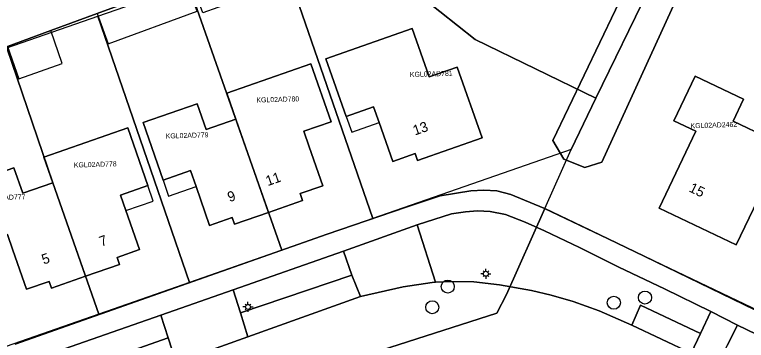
# Model space of a CAD drawing. Extents: x 124901 to 125496, y 515369 to 515789.
# Drawn here: x 125375.1 to 125447.9, y 515610.2 to 515642.6 of the extents above; entities that cross this region are included whole.
import ezdxf

# ---------------------------------------------------------------- set-up
doc = ezdxf.new("R2010")
doc.units = 0
for name, color, linetype in [('Gebouw', 7, 'Continuous'), ('Inrit', 7, 'Continuous'), ('Lichtmast', 7, 'Continuous'), ('Luifel', 7, 'Continuous'), ('Onbegroeid terrein', 7, 'Continuous'), ('Parkeren', 7, 'Continuous'), ('Perceelnummers', 7, 'Continuous'), ('Perceelsgrenzen', 7, 'Continuous'), ('Putten', 7, 'Continuous'), ('Teksten', 7, 'Continuous'), ('Vegetatie', 7, 'Continuous'), ('Voetpad', 7, 'Continuous'), ('Water', 7, 'Continuous'), ('Wegen lokale weg', 7, 'Continuous')]:
    doc.layers.add(name, color=color, linetype=linetype)

msp = doc.modelspace()

# ---------------------------------------------------------------- linework, layer by layer
at = {"layer": 'Gebouw'}
for points in [[(125410.844, 515633.424), (125411.39, 515631.867), (125412.745, 515628.002), (125414.976, 515628.779), (125415.215, 515628.092), (125421.655, 515630.332), (125419.151, 515637.368), (125416.368, 515636.398), (125414.688, 515641.218), (125406.105, 515638.212), (125408.119, 515632.469)], [(125404.595, 515637.692), (125396.253, 515634.781), (125397.145, 515632.216), (125400.378, 515622.922), (125403.778, 515624.105), (125403.539, 515624.794), (125405.794, 515625.578), (125404.439, 515629.441), (125403.893, 515630.998), (125406.608, 515631.951)], [(125442.903, 515630.992), (125439.24, 515623.35), (125446.92, 515619.7), (125450.354, 515626.876), (125453.96, 515625.15), (125456.99, 515631.45), (125451.94, 515633.89), (125450.218, 515630.285), (125446.609, 515632.009), (125447.646, 515634.179), (125442.84, 515636.475), (125440.719, 515632.035)], [(125394.169, 515631.178), (125393.28, 515633.72), (125387.91, 515631.86), (125389.902, 515626.132), (125392.638, 515627.083), (125393.186, 515625.506), (125394.53, 515621.64), (125396.77, 515622.42), (125397.004, 515621.748), (125400.378, 515622.922), (125397.145, 515632.216)], [(125385.565, 515617.762), (125385.325, 515618.452), (125387.565, 515619.232), (125386.202, 515623.109), (125385.661, 515624.647), (125388.392, 515625.607), (125386.375, 515631.342), (125378.036, 515628.433), (125378.931, 515625.866), (125382.17, 515616.578)], [(125375.063, 515627.374), (125369.695, 515625.503), (125371.671, 515619.772), (125374.406, 515620.725), (125374.949, 515619.167), (125376.301, 515615.284), (125378.556, 515616.07), (125378.79, 515615.399), (125382.17, 515616.578), (125378.931, 515625.866), (125375.951, 515624.827)]]:
    msp.add_lwpolyline(points, close=True, dxfattribs=at)
at = {"layer": 'Inrit'}
for points in [[(125409.531, 515614.567), (125413.775, 515615.518), (125416.656, 515615.975), (125416.988, 515615.988), (125415.182, 515621.683), (125407.837, 515619.085), (125408.68, 515616.693)], [(125389.667, 515612.721), (125390.406, 515610.469), (125391.211, 515608.016), (125398.324, 515610.559), (125397.585, 515612.935), (125396.869, 515615.238)], [(125447.051, 515611.707), (125444.402, 515613.086), (125443.375, 515610.9), (125442.448, 515608.927), (125445.037, 515607.711), (125446.027, 515609.707)]]:
    msp.add_lwpolyline(points, close=True, dxfattribs=at)
at = {"layer": 'Lichtmast'}
for p, q in [((125421.803, 515617.037), (125421.733, 515617.108)), ((125422.015, 515617.125), (125422.015, 515617.325)), ((125422.227, 515617.037), (125422.298, 515617.109)), ((125421.715, 515616.826), (125421.515, 515616.825)), ((125421.803, 515616.613), (125421.731, 515616.542)), ((125422.015, 515616.525), (125422.015, 515616.325)), ((125422.227, 515616.613), (125422.297, 515616.542)), ((125422.315, 515616.825), (125422.515, 515616.825)), ((125398.345, 515613.83), (125398.345, 515614.03)), ((125398.045, 515613.531), (125397.845, 515613.53)), ((125398.133, 515613.318), (125398.061, 515613.247)), ((125398.133, 515613.742), (125398.063, 515613.813)), ((125398.345, 515613.23), (125398.345, 515613.03)), ((125398.557, 515613.742), (125398.628, 515613.814)), ((125398.557, 515613.318), (125398.627, 515613.247)), ((125398.645, 515613.53), (125398.845, 515613.53))]:
    msp.add_line(p, q, dxfattribs=at)
for centre in [(125422.015, 515616.825), (125398.345, 515613.53)]:
    msp.add_circle(centre, 0.25, dxfattribs=at)
at = {"layer": 'Luifel'}
for points in [[(125392.17, 515645.96), (125383.332, 515642.723), (125384.436, 515639.707), (125393.275, 515642.944)], [(125374.409, 515639.418), (125375.532, 515636.224), (125379.873, 515637.75), (125378.729, 515641.005)], [(125411.39, 515631.867), (125410.844, 515633.424), (125408.119, 515632.469), (125408.665, 515630.912)], [(125389.902, 515626.132), (125390.45, 515624.555), (125393.186, 515625.506), (125392.638, 515627.083)], [(125388.392, 515625.607), (125385.661, 515624.647), (125386.202, 515623.109), (125388.914, 515624.062)]]:
    msp.add_lwpolyline(points, close=True, dxfattribs=at)
at = {"layer": 'Onbegroeid terrein'}
for points in [[(125429.798, 515702.583), (125421.887, 515685.97), (125412.818, 515667.163), (125406.911, 515654.851), (125405.36, 515651.11), (125405.288, 515650.687), (125401.387, 515649.315), (125397.596, 515647.927), (125395.619, 515647.21), (125396.839, 515643.846), (125393.848, 515642.761), (125392.627, 515646.124), (125392.17, 515645.96), (125383.332, 515642.723), (125378.729, 515641.005), (125374.409, 515639.418)], [(125490.925, 515630.677), (125448.027, 515651.268), (125444.728, 515651.073), (125443.321, 515649.329), (125433.556, 515627.939), (125431.85, 515627.386), (125429.766, 515628.208), (125428.663, 515630.094), (125436.481, 515646.34), (125445.451, 515665.509), (125446.119, 515665.186), (125448.787, 515670.727), (125448.083, 515671.163), (125452.441, 515680.669), (125457.131, 515690.833)], [(125375.169, 515609.812), (125392.301, 515615.845), (125406.232, 515620.771), (125414.095, 515623.452), (125417.469, 515624.564), (125420.516, 515625.062), (125421.795, 515625.138), (125423.115, 515625.058), (125424.478, 515624.722), (125427.773, 515623.362), (125434.165, 515620.296), (125439.534, 515617.72), (125451.494, 515611.999), (125464.767, 515605.477)]]:
    msp.add_lwpolyline(points, dxfattribs=at)
for points in [[(125411.39, 515631.867), (125410.844, 515633.424), (125408.119, 515632.469), (125406.105, 515638.212), (125414.688, 515641.218), (125416.368, 515636.398), (125419.151, 515637.368), (125421.655, 515630.332), (125415.215, 515628.092), (125414.976, 515628.779), (125412.745, 515628.002)], [(125393.28, 515633.72), (125394.169, 515631.178), (125397.145, 515632.216), (125396.253, 515634.781), (125404.595, 515637.692), (125406.608, 515631.951), (125403.893, 515630.998), (125404.439, 515629.441), (125405.794, 515625.578), (125403.539, 515624.794), (125403.778, 515624.105), (125400.378, 515622.922), (125397.004, 515621.748), (125396.77, 515622.42), (125394.53, 515621.64), (125393.186, 515625.506), (125392.638, 515627.083), (125389.902, 515626.132), (125387.91, 515631.86)], [(125439.24, 515623.35), (125442.903, 515630.992), (125440.719, 515632.035), (125442.84, 515636.475), (125447.646, 515634.179), (125446.609, 515632.009), (125450.218, 515630.285), (125451.94, 515633.89), (125456.99, 515631.45), (125453.96, 515625.15), (125450.354, 515626.876), (125446.92, 515619.7)], [(125369.695, 515625.503), (125375.063, 515627.374), (125375.951, 515624.827), (125378.931, 515625.866), (125378.036, 515628.433), (125386.375, 515631.342), (125388.392, 515625.607), (125385.661, 515624.647), (125386.202, 515623.109), (125387.565, 515619.232), (125385.325, 515618.452), (125385.565, 515617.762), (125382.17, 515616.578), (125378.79, 515615.399), (125378.556, 515616.07), (125376.301, 515615.284), (125374.949, 515619.167), (125374.406, 515620.725), (125371.671, 515619.772)]]:
    msp.add_lwpolyline(points, close=True, dxfattribs=at)
at = {"layer": 'Parkeren'}
for points in [[(125397.585, 515612.935), (125398.324, 515610.559), (125409.531, 515614.567), (125408.68, 515616.693)], [(125442.448, 515608.927), (125443.375, 515610.9), (125437.399, 515613.708), (125436.536, 515611.705)], [(125379.481, 515606.624), (125380.382, 515604.143), (125391.211, 515608.016), (125390.406, 515610.469)]]:
    msp.add_lwpolyline(points, close=True, dxfattribs=at)
at = {"layer": 'Perceelsgrenzen'}
for points in [[(125374.35, 515639.28), (125383.42, 515642.43), (125392.439, 515645.595), (125401.6, 515648.81), (125405.36, 515651.11), (125407.38, 515655.81), (125411.516, 515664.357), (125417.983, 515677.745), (125422.606, 515687.317), (125424.5, 515691.221)], [(125352.068, 515590.151), (125423.088, 515612.915), (125424.074, 515614.767), (125427.879, 515623.328), (125430.488, 515629.198), (125410.753, 515622.315), (125401.726, 515619.167), (125392.524, 515615.957), (125389.12, 515614.77), (125383.515, 515612.815), (125374.301, 515609.602)], [(125464.319, 515605.693), (125448.8, 515613.204), (125432.377, 515621.151), (125427.879, 515623.328), (125424.074, 515614.767), (125423.088, 515612.915), (125352.068, 515590.151)]]:
    msp.add_lwpolyline(points, dxfattribs=at)
for points in [[(125405.36, 515651.11), (125407.38, 515655.81), (125411.516, 515664.357), (125440.645, 515650.271), (125438.238, 515645.132), (125432.962, 515634.284), (125420.94, 515640.11), (125410.39, 515648.52)], [(125410.753, 515622.315), (125401.6, 515648.81), (125405.36, 515651.11), (125410.39, 515648.52), (125420.94, 515640.11), (125432.962, 515634.284), (125430.488, 515629.198)], [(125458.523, 515632.331), (125454.483, 515623.931), (125454.428, 515623.816), (125453.982, 515624.032), (125448.8, 515613.204), (125432.377, 515621.151), (125427.879, 515623.328), (125430.488, 515629.198), (125432.962, 515634.284), (125438.238, 515645.132), (125440.645, 515650.271), (125440.672, 515650.329), (125443.053, 515649.181), (125462.19, 515639.955), (125462.144, 515639.859), (125461.924, 515639.69), (125461.215, 515638.361), (125459.902, 515635.812), (125458.642, 515633.35)], [(125401.726, 515619.167), (125392.439, 515645.595), (125401.6, 515648.81), (125410.753, 515622.315)], [(125392.524, 515615.957), (125383.42, 515642.43), (125392.439, 515645.595), (125401.726, 515619.167)], [(125374.35, 515639.28), (125383.42, 515642.43), (125392.524, 515615.957), (125389.12, 515614.77), (125383.515, 515612.815), (125378.923, 515625.863)], [(125374.301, 515609.602), (125365.21, 515636.12), (125368.75, 515637.34), (125374.35, 515639.28), (125378.923, 515625.863), (125383.515, 515612.815)]]:
    msp.add_lwpolyline(points, close=True, dxfattribs=at)
at = {"layer": 'Putten'}
for centre in [(125418.22, 515615.55), (125437.84, 515614.46), (125416.68, 515613.5), (125434.74, 515613.95)]:
    msp.add_circle(centre, 0.65, dxfattribs=at)
at = {"layer": 'Vegetatie'}
msp.add_lwpolyline([(125374.409, 515639.418), (125378.729, 515641.005), (125383.332, 515642.723), (125392.17, 515645.96), (125392.627, 515646.124), (125395.619, 515647.21), (125397.596, 515647.927), (125401.387, 515649.315), (125405.288, 515650.687), (125405.36, 515651.11), (125406.911, 515654.851), (125389.202, 515648.653), (125381.355, 515645.99), (125372.6, 515642.854)], dxfattribs=at)
for points in [[(125443.375, 515610.9), (125444.402, 515613.086), (125439.775, 515615.327), (125435.239, 515617.475), (125431.321, 515619.424), (125427.838, 515621.112), (125425.93, 515621.968), (125423.967, 515622.72), (125422.437, 515623.018), (125421.168, 515623.076), (125419.985, 515622.996), (125418.603, 515622.78), (125415.182, 515621.683), (125416.988, 515615.988), (125418.599, 515616.052), (125420.799, 515616.025), (125423.373, 515615.736), (125426.538, 515615.179), (125428.506, 515614.693), (125430.698, 515614.077), (125433.273, 515613.146), (125436.536, 515611.705), (125437.399, 515613.708)], [(125397.585, 515612.935), (125408.68, 515616.693), (125407.837, 515619.085), (125396.869, 515615.238)], [(125390.406, 515610.469), (125389.667, 515612.721), (125378.669, 515608.861), (125379.481, 515606.624)], [(125462.026, 515601.858), (125463.045, 515604.005), (125447.051, 515611.707), (125446.027, 515609.707), (125445.037, 515607.711), (125451.427, 515604.548), (125452.479, 515606.551)]]:
    msp.add_lwpolyline(points, close=True, dxfattribs=at)
at = {"layer": 'Voetpad'}
for points in [[(125464.767, 515605.477), (125451.494, 515611.999), (125439.534, 515617.72), (125434.165, 515620.296), (125427.773, 515623.362), (125424.478, 515624.722), (125423.115, 515625.058), (125421.795, 515625.138), (125420.516, 515625.062), (125417.469, 515624.564), (125414.095, 515623.452), (125406.232, 515620.771), (125392.301, 515615.845), (125375.169, 515609.812)], [(125378.669, 515608.861), (125389.667, 515612.721), (125396.869, 515615.238), (125407.837, 515619.085), (125415.182, 515621.683), (125418.603, 515622.78), (125419.985, 515622.996), (125421.168, 515623.076), (125422.437, 515623.018), (125423.967, 515622.72), (125425.93, 515621.968), (125427.838, 515621.112), (125431.321, 515619.424), (125435.239, 515617.475), (125439.775, 515615.327), (125444.402, 515613.086), (125447.051, 515611.707), (125463.045, 515604.005)]]:
    msp.add_lwpolyline(points, dxfattribs=at)
at = {"layer": 'Water'}
msp.add_lwpolyline([(125457.131, 515690.833), (125452.441, 515680.669), (125448.083, 515671.163), (125448.787, 515670.727), (125446.119, 515665.186), (125445.451, 515665.509), (125436.481, 515646.34), (125428.663, 515630.094), (125429.766, 515628.208), (125431.85, 515627.386), (125433.556, 515627.939), (125443.321, 515649.329), (125444.728, 515651.073), (125454.573, 515658.231), (125461.167, 515672.009), (125466.419, 515682.908), (125469.241, 515688.71), (125472.559, 515695.531)], dxfattribs=at)
at = {"layer": 'Wegen lokale weg'}
for points in [[(125416.988, 515615.988), (125416.656, 515615.975), (125413.775, 515615.518), (125409.531, 515614.567), (125398.324, 515610.559), (125391.211, 515608.016), (125380.382, 515604.143), (125373.169, 515601.564), (125362.177, 515597.633), (125359.425, 515596.766), (125361.28, 515591.231)], [(125442.448, 515608.927), (125436.536, 515611.705), (125433.273, 515613.146), (125430.698, 515614.077), (125428.506, 515614.693), (125426.538, 515615.179), (125423.373, 515615.736), (125420.799, 515616.025), (125418.599, 515616.052), (125416.988, 515615.988)]]:
    msp.add_lwpolyline(points, dxfattribs=at)

# ---------------------------------------------------------------- texts
at = {"layer": 'Perceelnummers'}
for s, rotation, p in [('KGL02AD781', 1.63471, (125414.456, 515636.394)), ('KGL02AD780', 1.63453, (125399.187, 515633.854)), ('KGL02AD2462', 1.83322, (125442.377, 515631.291)), ('KGL02AD779', 1.63442, (125390.164, 515630.275)), ('KGL02AD778', 1.63432, (125381.028, 515627.39)), ('KGL02AD777', 1.63421, (125371.954, 515624.115))]:
    msp.add_text(s, height=0.5, rotation=rotation, dxfattribs=at).set_placement(p)
at = {"layer": 'Teksten'}
for s, rotation, p in [('13', 19.2, (125414.954, 515630.574)), ('11', 19.2, (125400.31, 515625.539)), ('15', 334.4, (125442.138, 515625.036)), ('9', 19.2, (125396.509, 515623.946)), ('7', 19.2, (125383.743, 515619.52)), ('5', 19.2, (125378.022, 515617.738))]:
    msp.add_text(s, height=1, rotation=rotation, dxfattribs=at).set_placement(p)

doc.saveas('drawing.dxf')
